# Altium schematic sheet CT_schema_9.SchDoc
size 281 x 153 mm
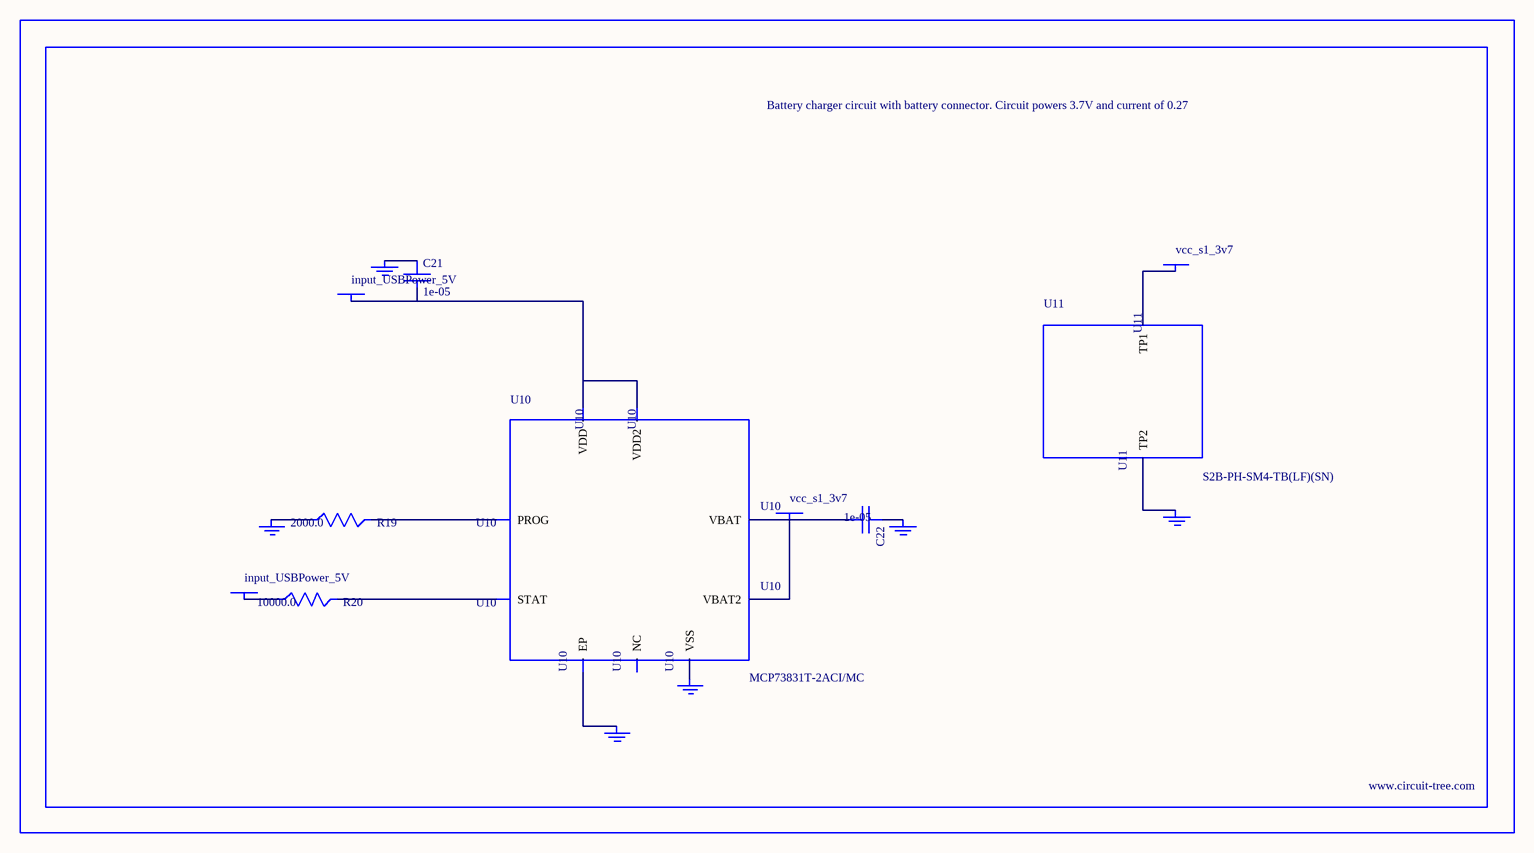
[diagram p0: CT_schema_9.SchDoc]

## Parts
BORDER8  (no value)
C21  1e-05  [C1206]
C22  1e-05  [C1206]
GND_INSTANCE_8_0  (no value)
GND_INSTANCE_8_1  (no value)
GND_INSTANCE_8_2  (no value)
GND_INSTANCE_8_3  (no value)
GND_INSTANCE_8_4  (no value)
GND_INSTANCE_8_5  (no value)
POWER_INSTANCE_8_0  input_USBPower_5V
POWER_INSTANCE_8_1  input_USBPower_5V
POWER_INSTANCE_8_2  vcc_s1_3v7
POWER_INSTANCE_8_3  vcc_s1_3v7
R19  2000.0  [R0603]
R20  10000.0  [R0603]
U10  MCP73831T-2ACI/MC  [DFN8_2X3MC]
U11  S2B-PH-SM4-TB(LF)(SN)  [JST-2-SMD]

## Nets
NetC21_1: C21.1 GND_INSTANCE_8_0.0(GND)
NetC21_2: C21.2 POWER_INSTANCE_8_0.0(PWR) U10.1(VDD) U10.2(VDD2)
NetC22_1: C22.1 GND_INSTANCE_8_1.0(GND)
NetC22_2: C22.2 POWER_INSTANCE_8_2.0(PWR) U10.3(VBAT) U10.4(VBAT2)
NetGND_INSTANCE_8_2_0: GND_INSTANCE_8_2.0(GND) R19.1
NetGND_INSTANCE_8_3_0: GND_INSTANCE_8_3.0(GND) U10.9(EP)
NetGND_INSTANCE_8_4_0: GND_INSTANCE_8_4.0(GND) U10.6(VSS)
NetGND_INSTANCE_8_5_0: GND_INSTANCE_8_5.0(GND) U11.2(TP2)
NetPOWER_INSTANCE_8_1_0: POWER_INSTANCE_8_1.0(PWR) R20.1
NetPOWER_INSTANCE_8_3_0: POWER_INSTANCE_8_3.0(PWR) U11.1(TP1)
NetR19_2: R19.2 U10.8(PROG)
NetR20_2: R20.2 U10.5(STAT)

Not connected (* = marked no-connect by the designer): U10 7(NC)

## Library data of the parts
BORDER8 = BORDER_PAGE8
C21 C22 = C1206C106K3RACTU
GND_INSTANCE_8_0-GND_INSTANCE_8_5 = GND
POWER_INSTANCE_8_0-POWER_INSTANCE_8_3 = PWR
R19 = RC0603JR-072KL
R20 = RC0603JR-0710KL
